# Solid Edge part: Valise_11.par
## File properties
Author: Bernard DUMAS
Template: Normal.par
Last saved by: FR026244
Revision: 5
Application: Solid Edge
Material: Bois, Chêne
Style de face: Jaune kaki
Style de remplissage: Liège
Style virtuel: Chêne verni
Coef. of Thermal Exp: 0.0
Thermal Conductivity: 0.0
Specific Heat: 0.0
Modulus of Elasticity: 0.0
Poission's Ratio: 0.0
Yield Stress: 0.0
Ultimate Stress: 0.0
Elongation: 0.0
Densité: 631.000 kg/m^3
Précision: 0.9900
Document Number: 11
Revision: a
Project Name: Slamson
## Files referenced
..\Valise_Salmson.asm
bD:\Documents and Settings\FR026244\Mes Documents\Bernard\Slamson\Valise-Salmson\Valise_Salmson.asm
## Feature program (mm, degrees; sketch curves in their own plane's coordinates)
sketch for "unnamed Protrusion 1" plane through (0, 0, 0) normal (0, -1, 0) x-axis (1, 0, 0)
extrude "unnamed Protrusion 1" add to key point symmetric
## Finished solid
Body 1: solid body, 6 faces, 12 edges, 8 vertices.
  Faces by surface: plane 6
  Edges by curve: line 12
Bounding box of the edges (mm): 21.972 x 830.000 x 35.000, from (438.8197, -415, 78) to (460.7918, 415, 113).
Planar faces by outward normal: +y 1, +z 1, -y 1, -z 1, oblique 2
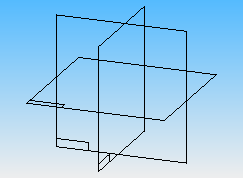
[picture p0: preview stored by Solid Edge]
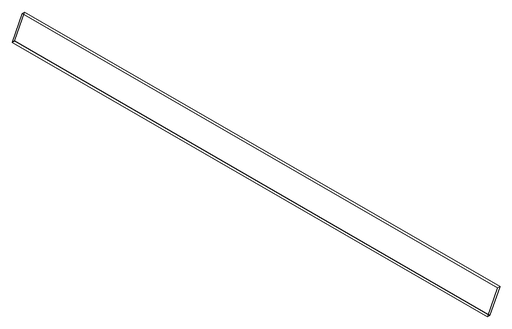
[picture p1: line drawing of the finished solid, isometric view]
